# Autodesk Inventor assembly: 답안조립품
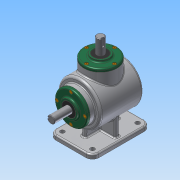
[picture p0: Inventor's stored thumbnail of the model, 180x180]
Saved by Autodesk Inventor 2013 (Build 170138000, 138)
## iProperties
Created: 2016-09
Part Number: 답안조립품
Document SubType Name: Assembly
Designer: Administrator
Author: Administrator
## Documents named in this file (14)
- C:\Users\Administrator\Desktop\460907V1015\답안조립품.iam
- C:\Users\Administrator\Desktop\460907V1015\1-본체.ipt
- C:\Users\Administrator\Desktop\460907V1015\커버.ipt
- C:\Users\Administrator\Desktop\460907V1015\M4.ipt
- C:\Users\Administrator\Desktop\460907V1015\베어링 6203.ipt
- C:\Users\Administrator\Desktop\460907V1015\오일실 17 32 8.ipt
- C:\Users\Administrator\Desktop\460907V1015\메인 축.ipt
- 메인 축.ipt
- C:\Users\Administrator\Desktop\460907V1015\서브 축.ipt
- 서브 축.ipt
- C:\Users\Administrator\Desktop\460907V1015\키 4x4.ipt
- C:\Users\Administrator\Desktop\460907V1015\키 5x5.ipt
- C:\Users\Administrator\Desktop\460907V1015\메인 베벨기어.ipt
- C:\Users\Administrator\Desktop\460907V1015\서브 베벨기어.ipt
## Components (9 placed, 2 different names)
1. 1-본체:1
2. M4:1
3. M4:2
4. M4:3
5. M4:4
6. M4:5
7. M4:6
8. M4:7
9. M4:8
